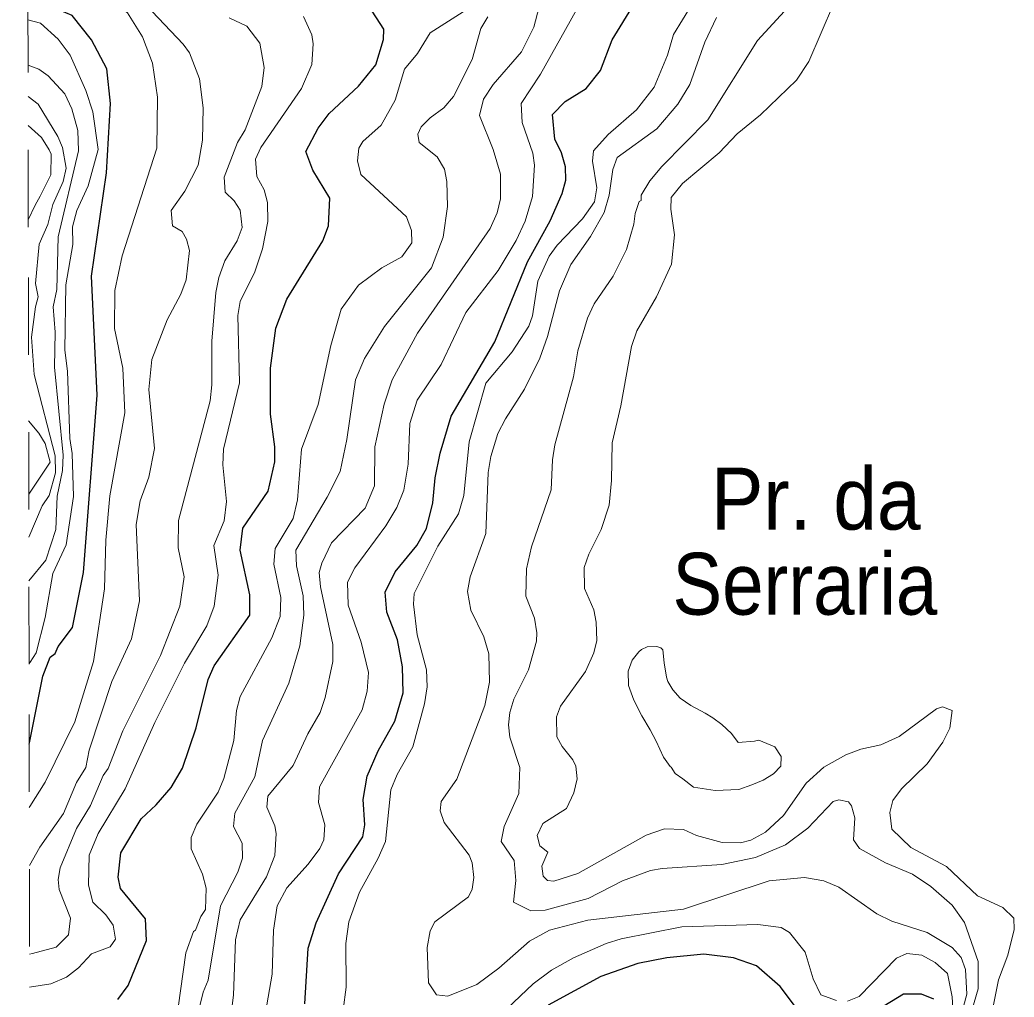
# Model space of a CAD drawing. Extents: x 474.5 to 500, y 7345.7 to 7373.4.
# Drawn here: x 474.522 to 475.808, y 7366.186 to 7367.449 of the extents above; entities that cross this region are included whole.
import ezdxf
from ezdxf.enums import TextEntityAlignment as Align

# ---------------------------------------------------------------- set-up
doc = ezdxf.new("R2010")
doc.units = 0
doc.header["$LTSCALE"] = 0.032
doc.linetypes.add('SHORT_DASHED', pattern=[2.7, 1.5, -1.2])
for name, color, linetype, lineweight in [('1', 7, 'Continuous', 25), ('15', 7, 'SHORT_DASHED', 13), ('2', 7, 'Continuous', 13), ('22', 7, 'SHORT_DASHED', 13)]:
    doc.layers.add(name, color=color, linetype=linetype, lineweight=lineweight)
doc.layers.add('61', color=7, linetype='Continuous')

msp = doc.modelspace()

# ---------------------------------------------------------------- linework, layer by layer
at = {"layer": '1'}
for points in [[(474.5343, 7366.5127), (474.5346, 7366.5143), (474.5518, 7366.6004), (474.5614, 7366.6248), (474.5676, 7366.6297), (474.5718, 7366.6387), (474.5901, 7366.6634), (474.6044, 7366.7344), (474.6219, 7366.9636), (474.6148, 7367.1177), (474.634, 7367.2513), (474.6395, 7367.3409), (474.6346, 7367.3854), (474.6149, 7367.4232), (474.5898, 7367.4546), (474.5326, 7367.4792)], [(474.6489, 7366.1826), (474.6622, 7366.2006), (474.6857, 7366.2586), (474.6844, 7366.2866), (474.6522, 7366.3259), (474.6491, 7366.3407), (474.6529, 7366.3721), (474.6789, 7366.416), (474.6983, 7366.4339), (474.7179, 7366.4567), (474.7324, 7366.4813), (474.7502, 7366.5335), (474.7658, 7366.596), (474.7732, 7366.6138), (474.8197, 7366.6794), (474.8197, 7366.7057), (474.8071, 7366.7635), (474.8104, 7366.7918), (474.843, 7366.8397), (474.8517, 7366.8774), (474.8517, 7366.8971), (474.8461, 7366.939), (474.8463, 7366.9985), (474.8533, 7367.0503), (474.8673, 7367.0877), (474.9139, 7367.1634), (474.9211, 7367.1824), (474.9231, 7367.2182), (474.901, 7367.2545), (474.8917, 7367.2785), (474.9077, 7367.3088), (474.922, 7367.3278), (474.96, 7367.3633), (474.9825, 7367.3907), (474.9921, 7367.4234), (474.9929, 7367.4369), (474.9727, 7367.4674)], [(474.9054, 7366.2817), (474.934, 7366.3451), (474.9657, 7366.3928), (474.9681, 7366.4083), (474.9658, 7366.4412), (474.971, 7366.4712), (474.9855, 7366.504), (475.0071, 7366.5424), (475.0177, 7366.579), (475.0169, 7366.6125), (475.0105, 7366.6476), (474.9968, 7366.6833), (474.9946, 7366.7092), (475.0076, 7366.7351), (475.0355, 7366.7694), (475.0478, 7366.7913), (475.0559, 7366.8247), (475.0591, 7366.8567), (475.0654, 7366.8889), (475.0797, 7366.9365), (475.1364, 7367.0325), (475.1786, 7367.136), (475.2076, 7367.1891), (475.2235, 7367.2242), (475.2282, 7367.2415), (475.2274, 7367.259), (475.2225, 7367.2769), (475.2137, 7367.2948), (475.2108, 7367.3264), (475.2272, 7367.3434), (475.2543, 7367.3602), (475.2729, 7367.3835), (475.2879, 7367.4232), (475.3168, 7367.4701)], [(474.8907, 7366.177), (474.8951, 7366.2488), (474.9054, 7366.2817)], [(475.5289, 7366.1677), (475.5051, 7366.1993), (475.4745, 7366.226), (475.4449, 7366.2364), (475.4065, 7366.2412), (475.3587, 7366.2365), (475.321, 7366.2288), (475.2732, 7366.2123), (475.2053, 7366.1753)], [(475.7036, 7366.1828), (475.6877, 7366.1892), (475.6647, 7366.1894), (475.6316, 7366.1689)]]:
    msp.add_lwpolyline(points, dxfattribs=at)
at = {"layer": '15'}
for points in [[(475.3534, 7366.6345), (475.355, 7366.6177), (475.3583, 7366.5993), (475.36, 7366.5934), (475.3663, 7366.5826), (475.3759, 7366.5721), (475.3897, 7366.5625), (475.408, 7366.5525), (475.4181, 7366.5467), (475.4298, 7366.5379), (475.4423, 7366.5262), (475.451, 7366.5145), (475.4719, 7366.5166), (475.4775, 7366.5176), (475.4881, 7366.5135), (475.4983, 7366.5089), (475.5066, 7366.4964), (475.5062, 7366.4839), (475.4967, 7366.4743), (475.483, 7366.4659), (475.4683, 7366.4599), (475.4516, 7366.4539), (475.4209, 7366.4527), (475.3931, 7366.457), (475.3791, 7366.4677), (475.3694, 7366.4747), (475.3641, 7366.4827), (475.3628, 7366.4838), (475.3543, 7366.4959), (475.3449, 7366.5165), (475.337, 7366.5311), (475.3264, 7366.5491), (475.3158, 7366.5692), (475.3089, 7366.5885), (475.3085, 7366.607), (475.3136, 7366.6211), (475.3222, 7366.6318), (475.3259, 7366.6351), (475.3333, 7366.6382), (475.3457, 7366.639)], [(475.3457, 7366.639), (475.3507, 7366.6371), (475.3534, 7366.6345)]]:
    msp.add_lwpolyline(points, dxfattribs=at)
at = {"layer": '2'}
for points in [[(474.5325, 7367.5322), (474.5595, 7367.5256), (474.5823, 7367.5158), (474.6042, 7367.5025), (474.6614, 7367.4578), (474.6808, 7367.4269), (474.6937, 7367.393), (474.7001, 7367.349), (474.6993, 7367.283), (474.6546, 7367.1439), (474.645, 7367.0992), (474.6445, 7367.0499), (474.6555, 7366.9988), (474.6578, 7366.941), (474.6386, 7366.8337), (474.6332, 7366.7762), (474.6315, 7366.7132), (474.6172, 7366.6195), (474.5933, 7366.5413), (474.5551, 7366.4632), (474.5351, 7366.4318), (474.5344, 7366.4307)], [(474.5346, 7366.3556), (474.548, 7366.3795), (474.5787, 7366.4228), (474.5955, 7366.4628), (474.6076, 7366.4823), (474.6116, 7366.5046), (474.6409, 7366.5935), (474.6664, 7366.6489), (474.677, 7366.6979), (474.6724, 7366.7964), (474.6775, 7366.8272), (474.6891, 7366.8576), (474.6961, 7366.8947), (474.689, 7366.9709), (474.6929, 7367.0099), (474.7127, 7367.061), (474.7302, 7367.0941), (474.7373, 7367.1129), (474.7416, 7367.1505), (474.7377, 7367.1655), (474.732, 7367.1753), (474.7195, 7367.1824), (474.7177, 7367.2024), (474.7354, 7367.2274), (474.7529, 7367.2612), (474.7583, 7367.2935), (474.7592, 7367.3352), (474.7543, 7367.3726), (474.7415, 7367.4061), (474.7332, 7367.4175), (474.6527, 7367.5027)], [(475.5353, 7367.4872), (475.4758, 7367.4221), (475.4116, 7367.3195), (475.3522, 7367.2594), (475.3367, 7367.2406), (475.3256, 7367.2223), (475.3255, 7367.2154), (475.323, 7367.2139), (475.3176, 7367.1986), (475.316, 7367.1847), (475.3063, 7367.1519), (475.2891, 7367.1175), (475.2648, 7367.0817), (475.2562, 7367.0631), (475.2435, 7367.0208), (475.2378, 7366.9876), (475.2139, 7366.8995), (475.2107, 7366.8802), (475.209, 7366.8411), (475.1836, 7366.7676), (475.1772, 7366.7391), (475.1764, 7366.7039), (475.1874, 7366.6756), (475.1907, 7366.6564), (475.1899, 7366.6458), (475.1797, 7366.6086), (475.1608, 7366.5706), (475.1556, 7366.5536), (475.154, 7366.5375), (475.1557, 7366.5214), (475.1684, 7366.4823), (475.1672, 7366.4489), (475.1482, 7366.4062), (475.1444, 7366.3865), (475.1612, 7366.3623), (475.1636, 7366.3363), (475.1605, 7366.3084), (475.183, 7366.297), (475.2013, 7366.2978), (475.2568, 7366.3131), (475.3011, 7366.3358), (475.3377, 7366.3491), (475.3525, 7366.352), (475.4297, 7366.3569), (475.4731, 7366.3661), (475.512, 7366.3822), (475.5411, 7366.404)], [(475.1935, 7367.4658), (475.1868, 7367.4396), (475.1708, 7367.4075), (475.1343, 7367.3654), (475.1218, 7367.3462), (475.1166, 7367.3253), (475.1342, 7367.2812), (475.1436, 7367.2494), (475.1436, 7367.2173), (475.1392, 7367.1994), (475.13, 7367.179), (475.0364, 7367.0439), (475.0035, 7366.9836), (474.9931, 7366.9521), (474.981, 7366.8971), (474.9808, 7366.8465), (474.9684, 7366.8176), (474.9249, 7366.773), (474.9124, 7366.7463), (474.9092, 7366.7344), (474.9108, 7366.716), (474.9267, 7366.6413), (474.9266, 7366.6192), (474.9171, 7366.573), (474.9105, 7366.5533), (474.8946, 7366.5257), (474.8755, 7366.485), (474.8428, 7366.4452), (474.8414, 7366.4313), (474.8518, 7366.4068), (474.8534, 7366.3972), (474.8517, 7366.3687), (474.841, 7366.3409), (474.807, 7366.2855), (474.801, 7366.2598), (474.7982, 7366.1879), (474.7934, 7366.147)], [(474.8413, 7366.1755), (474.8485, 7366.2154), (474.8502, 7366.272), (474.8549, 7366.3036), (474.8675, 7366.327), (474.8951, 7366.3573), (474.9099, 7366.3776), (474.9153, 7366.3889), (474.9164, 7366.4084), (474.9084, 7366.4373), (474.9094, 7366.4575), (474.9648, 7366.5568), (474.9714, 7366.5812), (474.9729, 7366.6052), (474.9634, 7366.6446), (474.9467, 7366.6924), (474.9459, 7366.7218), (474.9553, 7366.7403), (474.9953, 7366.7947), (475.0095, 7366.8185), (475.0185, 7366.8407), (475.024, 7366.8743), (475.0264, 7366.9272), (475.0358, 7366.9574), (475.0669, 7367.0035), (475.0989, 7367.0706), (475.1404, 7367.125), (475.1637, 7367.1636), (475.1754, 7367.1886), (475.1851, 7367.2207), (475.1875, 7367.2612), (475.1852, 7367.2764), (475.1717, 7367.3163), (475.1702, 7367.3406), (475.1954, 7367.3785), (475.248, 7367.4726)], [(475.3903, 7367.4679), (475.3674, 7367.4301), (475.3594, 7367.403), (475.3423, 7367.3619), (475.3193, 7367.3326), (475.2827, 7367.3007), (475.264, 7367.2794), (475.2626, 7367.2662), (475.2682, 7367.2316), (475.265, 7367.2137), (475.2496, 7367.1918), (475.2169, 7367.1575), (475.2064, 7367.1432), (475.1917, 7367.1112), (475.1851, 7367.0661), (475.1801, 7367.0527), (475.1588, 7367.0199), (475.1246, 7366.979), (475.1031, 7366.9035), (475.096, 7366.8342), (475.0894, 7366.8102), (475.0625, 7366.7686), (475.032, 7366.7071), (475.0313, 7366.6935), (475.036, 7366.6538), (475.048, 7366.6087), (475.0487, 7366.5867), (475.0455, 7366.5648)], [(475.2872, 7366.8533), (475.2881, 7366.9022), (475.2993, 7366.9498), (475.3129, 7367.0264), (475.3198, 7367.0467), (475.3452, 7367.0908), (475.3646, 7367.1331), (475.3687, 7367.171), (475.3639, 7367.2043), (475.3641, 7367.2194), (475.3789, 7367.2374), (475.4262, 7367.2768), (475.4496, 7367.3017), (475.4797, 7367.3262), (475.5263, 7367.3711), (475.5424, 7367.3952), (475.5742, 7367.4691)], [(474.889, 7367.4531), (474.8996, 7367.4295), (474.9012, 7367.418), (474.8995, 7367.3912), (474.8863, 7367.36), (474.8336, 7367.2838), (474.827, 7367.2689), (474.8287, 7367.2462), (474.8379, 7367.2293), (474.8422, 7367.2126), (474.8429, 7367.1883), (474.8359, 7367.1527), (474.826, 7367.1232), (474.807, 7367.0848), (474.8039, 7367.0666), (474.8062, 7366.9796), (474.7855, 7366.894), (474.7847, 7366.8736), (474.7894, 7366.8261), (474.7862, 7366.8012), (474.7728, 7366.7695), (474.7784, 7366.7309), (474.7735, 7366.6908), (474.7638, 7366.6653), (474.7351, 7366.6174), (474.6967, 7366.5405), (474.6585, 7366.4547), (474.6233, 7366.3969), (474.6116, 7366.369), (474.6108, 7366.3302), (474.6164, 7366.3084), (474.6335, 7366.2918), (474.6426, 7366.2786), (474.6457, 7366.2604), (474.6389, 7366.2506), (474.6146, 7366.2417), (474.598, 7366.2235), (474.5823, 7366.2114), (474.5624, 7366.2029), (474.5348, 7366.1986)], [(474.5348, 7366.2409), (474.5384, 7366.2419), (474.5691, 7366.25), (474.5852, 7366.2661), (474.5876, 7366.2876), (474.5729, 7366.3245), (474.5717, 7366.3378), (474.5742, 7366.3525), (474.5955, 7366.4036), (474.6134, 7366.4331), (474.6297, 7366.4719), (474.6362, 7366.481), (474.6553, 7366.5297), (474.704, 7366.627), (474.7288, 7366.6911), (474.7345, 7366.729), (474.7268, 7366.7664), (474.7271, 7366.8018), (474.768, 7366.9565), (474.7704, 7366.9772), (474.7704, 7367.0335), (474.7756, 7367.0964), (474.7792, 7367.1157), (474.787, 7367.1375), (474.8029, 7367.1631), (474.8096, 7367.1806), (474.8071, 7367.203), (474.7992, 7367.215), (474.7877, 7367.2261), (474.7863, 7367.2453), (474.8036, 7367.2904), (474.8134, 7367.3069), (474.8349, 7367.3625), (474.8381, 7367.3873), (474.8324, 7367.4189), (474.8158, 7367.4409), (474.7926, 7367.4513)], [(474.7435, 7366.1287), (474.7592, 7366.1919), (474.7655, 7366.2076), (474.7816, 7366.3036), (474.8041, 7366.347), (474.8101, 7366.365), (474.8094, 7366.3847), (474.7983, 7366.4063), (474.7999, 7366.4233), (474.8259, 7366.4703), (474.8358, 7366.5174), (474.8698, 7366.5916), (474.8843, 7366.6395), (474.8892, 7366.6794), (474.8884, 7366.7044), (474.8797, 7366.7432), (474.8789, 7366.7634), (474.9196, 7366.8317), (474.9362, 7366.8649), (474.945, 7366.9064), (474.9563, 7366.9833), (474.9679, 7367.0112), (474.9937, 7367.0524), (475.0543, 7367.1283), (475.0694, 7367.1679), (475.075, 7367.2075), (475.0742, 7367.2399), (475.071, 7367.2558), (475.0615, 7367.2717), (475.0384, 7367.2902), (475.0368, 7367.3011), (475.041, 7367.3104), (475.0525, 7367.3224), (475.0704, 7367.335), (475.0829, 7367.3498), (475.1068, 7367.3976), (475.1181, 7367.4375), (475.1272, 7367.4529)], [(475.0953, 7367.4593), (475.0528, 7367.4321), (475.0361, 7367.4052), (475.0193, 7367.3852), (475.0072, 7367.3452), (474.9893, 7367.3129), (474.9656, 7367.2915), (474.9602, 7367.2828), (474.9587, 7367.2668), (474.9632, 7367.249), (475.022, 7367.1941), (475.0287, 7367.1767), (475.0288, 7367.1604), (475.016, 7367.1427), (474.9903, 7367.1281), (474.9601, 7367.1057), (474.9377, 7367.075), (474.9244, 7367.028), (474.9077, 7366.9517), (474.8861, 7366.894)], [(475.2945, 7367.2708), (475.3455, 7367.3078), (475.3728, 7367.3399), (475.3882, 7367.3653), (475.4076, 7367.42), (475.4227, 7367.4519)], [(474.5341, 7366.616), (474.5357, 7366.6185), (474.5434, 7366.6305), (474.5548, 7366.6763), (474.5647, 7366.7331), (474.5821, 7366.7703), (474.5916, 7366.8328), (474.59, 7366.8884), (474.5869, 7366.9078), (474.5836, 7366.9948), (474.5805, 7367.022), (474.5814, 7367.1063), (474.5908, 7367.1583), (474.5901, 7367.1811), (474.5959, 7367.2022), (474.6105, 7367.2345), (474.6236, 7367.2811), (474.6164, 7367.3298), (474.6076, 7367.3577), (474.5873, 7367.4032), (474.5718, 7367.424), (474.5488, 7367.4447), (474.5326, 7367.4488)], [(474.5327, 7367.3903), (474.5468, 7367.3849), (474.5589, 7367.3765), (474.5804, 7367.3532), (474.5893, 7367.3338), (474.5971, 7367.3059), (474.5981, 7367.2797), (474.5717, 7367.1684), (474.57, 7367.1004), (474.5654, 7367.0777), (474.5678, 7367.0452), (474.567, 7366.9997), (474.578, 7366.8863), (474.5772, 7366.8663), (474.5702, 7366.8333), (474.5686, 7366.7902), (474.5558, 7366.7505), (474.5339, 7366.7235)], [(474.5338, 7366.7801), (474.5508, 7366.8208), (474.5599, 7366.834), (474.5683, 7366.8633), (474.5676, 7366.8853), (474.5406, 7366.9905), (474.5374, 7367.0385), (474.5422, 7367.0777), (474.5459, 7367.091), (474.5422, 7367.1079), (474.547, 7367.159), (474.5582, 7367.1843), (474.5647, 7367.2101), (474.578, 7367.2399), (474.5821, 7367.2573), (474.5774, 7367.284), (474.5712, 7367.2981), (474.5458, 7367.3398), (474.5328, 7367.3497)], [(474.533, 7367.3124), (474.5501, 7367.2966), (474.5599, 7367.2809), (474.5628, 7367.2754), (474.5621, 7367.2484), (474.5486, 7367.2209), (474.5419, 7367.2094), (474.5331, 7367.1902)], [(475.7365, 7366.1528), (475.7466, 7366.1892), (475.7447, 7366.2213), (475.7393, 7366.2366), (475.7276, 7366.2499), (475.6953, 7366.2692), (475.6495, 7366.2836), (475.63, 7366.293), (475.5811, 7366.3275), (475.5617, 7366.336), (475.5366, 7366.34), (475.491, 7366.3359), (475.3801, 7366.2994), (475.2563, 7366.285), (475.207, 7366.272), (475.1809, 7366.2577), (475.1414, 7366.2229), (475.1131, 7366.2019), (475.0753, 7366.1869), (475.0607, 7366.1884), (475.0505, 7366.2042), (475.0488, 7366.2497), (475.0527, 7366.2712), (475.0588, 7366.283), (475.102, 7366.3152), (475.107, 7366.3253), (475.1093, 7366.34), (475.107, 7366.359), (475.1029, 7366.3689), (475.0708, 7366.4112), (475.0656, 7366.4262), (475.0667, 7366.4383), (475.0869, 7366.4675), (475.1231, 7366.5624), (475.1292, 7366.5928), (475.1284, 7366.6294), (475.122, 7366.6514), (475.105, 7366.6856), (475.1011, 7366.7099), (475.1045, 7366.729), (475.1244, 7366.7847), (475.1278, 7366.8639), (475.131, 7366.8844), (475.1403, 7366.9142), (475.1499, 7366.9333), (475.1746, 7366.9716), (475.1946, 7367.0116), (475.2045, 7367.0394), (475.2199, 7367.0985), (475.2345, 7367.1328), (475.2601, 7367.1689), (475.2777, 7367.2), (475.284, 7367.2221), (475.2888, 7367.2555), (475.2945, 7367.2708)], [(474.5337, 7366.8358), (474.5613, 7366.8772), (474.5548, 7366.901), (474.5469, 7366.9144), (474.5335, 7366.9306), (474.5335, 7366.9307)], [(474.8861, 7366.894), (474.8813, 7366.8285), (474.8756, 7366.8043), (474.8522, 7366.7653), (474.8506, 7366.7453), (474.8597, 7366.702), (474.8586, 7366.6774), (474.8481, 7366.6502), (474.8069, 7366.5743), (474.8023, 7366.556), (474.799, 7366.5171), (474.7859, 7366.4683), (474.7786, 7366.4507), (474.7511, 7366.4093), (474.7438, 7366.3918), (474.7435, 7366.3773), (474.7584, 7366.3446), (474.763, 7366.3262), (474.7623, 7366.2988), (474.7561, 7366.2897), (474.7494, 7366.2723), (474.7465, 7366.2704), (474.7369, 7366.243), (474.7233, 7366.1476)], [(475.7792, 7366.1668), (475.7875, 7366.2079), (475.7995, 7366.2398), (475.8076, 7366.2728), (475.8074, 7366.2874), (475.7932, 7366.3015), (475.7601, 7366.3163), (475.7203, 7366.3545), (475.6739, 7366.3788), (475.6495, 7366.4025), (475.6471, 7366.424), (475.6509, 7366.4396), (475.6621, 7366.4548), (475.6951, 7366.4873), (475.7155, 7366.5153), (475.7245, 7366.5334), (475.7276, 7366.556), (475.7151, 7366.5609), (475.7073, 7366.558), (475.6588, 7366.5226), (475.6354, 7366.5116), (475.6095, 7366.5059), (475.5899, 7366.4986), (475.5615, 7366.4827), (475.5387, 7366.4623), (475.5095, 7366.4204), (475.486, 7366.3989), (475.4673, 7366.3886), (475.4538, 7366.3851), (475.4302, 7366.3854), (475.3971, 7366.3946), (475.3801, 7366.4022), (475.3558, 7366.403), (475.3317, 7366.3949), (475.2437, 7366.3454), (475.2125, 7366.3353), (475.2044, 7366.3361), (475.1989, 7366.342), (475.1972, 7366.3548), (475.2049, 7366.3729), (475.1945, 7366.3812), (475.1909, 7366.3945), (475.1985, 7366.4099), (475.2289, 7366.4293), (475.2382, 7366.4495), (475.2426, 7366.4677), (475.2411, 7366.4839), (475.2371, 7366.4923), (475.2233, 7366.5094), (475.2162, 7366.5222), (475.2159, 7366.5477), (475.2211, 7366.5618), (475.2536, 7366.6063), (475.2642, 7366.6307), (475.2682, 7366.6466), (475.2674, 7366.6701), (475.2642, 7366.686), (475.2522, 7366.7137), (475.2518, 7366.7408), (475.2579, 7366.7583), (475.2737, 7366.7899), (475.2839, 7366.8214), (475.2872, 7366.8533)], [(475.0455, 7366.5648), (475.0304, 7366.5091), (475.0099, 7366.4732), (475.0017, 7366.4536), (474.995, 7366.3869), (474.9856, 7366.3653), (474.9611, 7366.3212), (474.9475, 7366.2829), (474.9435, 7366.2549), (474.9442, 7366.1986), (474.9402, 7366.1691)], [(475.5411, 7366.404), (475.5738, 7366.4383), (475.5811, 7366.4405), (475.5935, 7366.4381), (475.5973, 7366.433), (475.6015, 7366.4172), (475.6, 7366.3889), (475.6078, 7366.3778), (475.6413, 7366.3592), (475.6761, 7366.3443), (475.6999, 7366.3285), (475.7273, 7366.3045), (475.7435, 7366.2818), (475.7611, 7366.2315), (475.7611, 7366.1964), (475.7357, 7366.109)], [(475.1522, 7366.1707), (475.1859, 7366.2027), (475.2096, 7366.2202), (475.2381, 7366.2365), (475.2803, 7366.255), (475.2995, 7366.2609), (475.378, 7366.2762), (475.4762, 7366.2795), (475.5064, 7366.2755), (475.517, 7366.269), (475.5376, 7366.2435), (475.5479, 7366.2093), (475.5578, 7366.1885), (475.5779, 7366.1812)], [(475.5922, 7366.1805), (475.6073, 7366.1862), (475.6555, 7366.2358), (475.6687, 7366.2419), (475.6883, 7366.2396), (475.7056, 7366.2305), (475.7213, 7366.2161), (475.7276, 7366.1857), (475.7292, 7366.156)]]:
    msp.add_lwpolyline(points, dxfattribs=at)
at = {"layer": '22'}
msp.add_lwpolyline([(474.5381, 7364.3565), (474.5371, 7364.9213), (474.5361, 7365.4862), (474.5351, 7366.0511), (474.5341, 7366.616), (474.5331, 7367.1808), (474.5321, 7367.7457), (474.5311, 7368.3105), (474.5301, 7368.8754), (474.5291, 7369.4403), (474.5281, 7370.0051), (474.5272, 7370.57), (474.5262, 7371.1349), (474.5252, 7371.6997), (474.5242, 7372.2646), (474.5232, 7372.8295), (474.5222, 7373.3943)], dxfattribs=at)

# ---------------------------------------------------------------- texts
at = {"layer": '61'}
for s, width, p in [(' Pr. da', 0.95, (475.5371, 7366.7899)), ('Serraria', 0.9, (475.5371, 7366.6799))]:
    msp.add_text(s, height=0.08, dxfattribs=dict(at, width=width)).set_placement(p, align=Align.CENTER)

doc.saveas('drawing.dxf')
